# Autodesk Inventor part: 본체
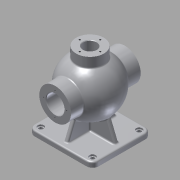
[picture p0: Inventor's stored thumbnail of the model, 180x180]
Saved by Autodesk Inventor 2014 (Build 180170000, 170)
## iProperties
Created: 2015-10
Part Number: 본체
Material: Aluminum 6061
Document SubType Name: Modeling
Designer: youjin15
Density: 2.71 g/cm^3
Appearance: Aluminum - Flat
Mass: 1509.57 g
Surface Area: 1153.7 cm^2
Volume: 557.037 cm^3
Author: youjin15
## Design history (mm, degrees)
sketch "Sketch1"
  geometry: L1 (45.5, -62.5)-(-45.5, -62.5); L2 (-57.5, -50.5)-(-57.5, 50.5); L3 (-45.5, 62.5)-(45.5, 62.5); L4 (57.5, 50.5)-(57.5, -50.5); L5 (57.5, -62.5)-(-57.5, 62.5); L6 (-57.5, -62.5)-(57.5, 62.5); A1 r 12 centre (-45.5, 50.5) between (-45.5, 62.5) and (-57.5, 50.5); A2 r 12 centre (45.5, 50.5) between (57.5, 50.5) and (45.5, 62.5); A3 r 12 centre (45.5, -50.5) between (45.5, -62.5) and (57.5, -50.5); A4 r 12 centre (-45.5, -50.5) between (-57.5, -50.5) and (-45.5, -62.5); 1 further point
  constraints: 12 end point, 8 point on circle, 8 point on line, 8 tangent, 4 centre point, 3 equal radius, 2 midpoint, 2 parallel, 1 horizontal, 1 perpendicular
  dimensions: "d0" = 115 distance of L5.end L6.end; "d1" = 125 distance of L6.start L5.end; "d2" = 12 radius of A1
extrude "Extrusion1" new body sketch "Sketch1" distance "d3" = 10; taper "d4" = 0 deg
sketch "Sketch2"
  geometry: L1 (53, 85)-(-53, 85); L2 (45.5, 0)-(-45.5, 0) reference; A1 r 53 centre (0, 85) between (53, 85) and (-53, 85); 4 further points
  constraints: 2 end point, 2 midpoint, 2 point on circle, 2 vertical alignment, 1 centre point, 1 horizontal
  dimensions: "d5" = 106 distance of L1.start L1.end; "d6" = 53 radius of A1; "d7" = 85 distance between parallel lines of L2 L1; "d9" = 43 distance of A1.centre point (0, 128)
revolve "Revolution1" sketch "Sketch2" stored, may be unused: angle "d10" = 90 deg
sketch "Sketch3"
  geometry: L1 (68, 85)-(-68, 85); L2 (-45.5, 0)-(45.5, 0) reference; L3 (68, 85)-(68, 116); L4 (68, 116)-(42.988, 116); L5 (-68, 85)-(-68, 116); L6 (-68, 116)-(-42.988, 116); A1 r 53 centre (0, 85) between (42.988, 116) and (-42.988, 116) reference; A2 r 53 centre (0, 85) between (-42.988, 116) and (-53, 85); A3 r 53 centre (0, 85) between (53, 85) and (42.988, 116); 2 further points
  constraints: 10 end point, 8 point on circle, 4 perpendicular, 2 centre point, 2 coincident, 2 concentric, 1 collinear, 1 horizontal, 1 midpoint, 1 point on line, 1 vertical alignment
  dimensions: "d11" = 136 distance of L1.start L1.end; "d12" = 85 distance between parallel lines of L2 L1; "d13" = 62 diameter of L4 L1
revolve "Revolution2" sketch "Sketch3" stored, may be unused: angle "d14" = 90 deg
hole "Hole1" diameter "d17" = 35; stored, may be unused: countersink angle "d21" = 90 deg, drill point angle "d23" = 0 deg; dims "d15" = 10, "d16" = 10, "d18" = 6, "d19" = 4, "d20" = 2, "d22" = 8
sketch "Sketch4"
  geometry: L1 (-43, 85)-(43, 85); L2 (45.5, 0)-(-45.5, 0) reference; A1 r 53 centre (0, 85) between (42.988, 116) and (42.988, 54) reference; A2 r 43 centre (0, 85) between (43, 85) and (-43, 85); 2 further points
  constraints: 2 end point, 2 point on circle, 1 centre point, 1 coincident, 1 horizontal, 1 midpoint, 1 vertical alignment
  dimensions: "d24" = 43 radius of A2; "d25" = 85 distance between parallel lines of L2 L1
revolve "Revolution3" sketch "Sketch4" stored, may be unused: angle "d26" = 90 deg
sketch "Sketch5"
  geometry: L1 (42.988, 116)-(42.988, 54) reference; L2 (68, 54)-(68, 116) reference; L3 (39.278, 102.5)-(68, 102.5) reference; L4 (39.278, 67.5)-(68, 67.5) reference; L5 (42.988, 116)-(68, 116) reference; L6 (68, 116)-(68, 102.5) reference; L7 (68, 102.5)-(39.278, 102.5) reference; L8 (-39.278, 102.5)-(-68, 102.5) reference; L9 (-68, 102.5)-(-68, 116) reference; L10 (-68, 116)-(-42.988, 116) reference; L11 (68, 54)-(42.988, 54) reference; L12 (-42.988, 54)-(-68, 54) reference; L13 (-68, 54)-(-68, 67.5) reference; L14 (-68, 67.5)-(-39.278, 67.5) reference; L15 (39.278, 67.5)-(68, 67.5) reference; L16 (68, 67.5)-(68, 54) reference; L17 (57.5, 10)-(57.5, 0) reference; L18 (57.5, 0)-(-57.5, 0) reference; L19 (-57.5, 0)-(-57.5, 10) reference; L20 (-57.5, 10)-(57.5, 10) reference; L21 (0, 85)-(68, 85); L22 (52, 85)-(52, 103.5); L23 (52, 103.5)-(50.25, 103.5); L24 (50.25, 103.5)-(50.25, 85); A1 r 43 centre (0, 85) between (39.278, 102.5) and (-39.278, 102.5) reference; A2 r 53 centre (0, 85) between (42.988, 116) and (-42.988, 116) reference; A3 r 53 centre (0, 85) between (-42.988, 54) and (42.988, 54) reference; A4 r 43 centre (0, 85) between (-39.278, 67.5) and (39.278, 67.5) reference; 1 further point
  constraints: 8 end point, 3 perpendicular, 2 point on line, 1 midpoint
  dimensions: "d27" = 1.75 distance of L22.end L23.end; "d28" = 16 distance between parallel lines of L2 L22; "d29" = 37 diameter of L23 L21
revolve "Revolution4" sketch "Sketch5" stored, may be unused: angle "d30" = 90 deg
workplane "Work Plane1"
sketch "Sketch6"
  geometry: C1 r 27 at (0, 0); 1 further point
  constraints: 1 centre point, 1 coincident
  dimensions: "d33" = 54 diameter of C1
extrude "Extrusion2" join sketch "Sketch6" stored distance "d34" = 10; taper "d35" = 0 deg
hole "Hole2" diameter "d38" = 26; stored, may be unused: countersink angle "d42" = 90 deg, drill point angle "d44" = 0 deg; dims "d36" = 10, "d37" = 10, "d39" = 6, "d40" = 4, "d41" = 2, "d43" = 8
sketch "Sketch11"
  geometry: L1 (-27, 130.607)-(-27, 150) reference; L2 (-27, 150)-(-13, 150) reference; L3 (-13, 150)-(-13, 125.988) reference; L4 (-39.278, 102.5)-(-68, 102.5) reference; L5 (-68, 102.5)-(-68, 116) reference; L6 (-68, 116)-(-42.988, 116) reference; L7 (52, 103.5)-(50.25, 103.5) reference; L8 (50.25, 103.5)-(50.25, 102.5) reference; L9 (50.25, 102.5)-(39.278, 102.5) reference; L10 (13, 125.988)-(13, 150) reference; L11 (13, 150)-(27, 150) reference; L12 (27, 150)-(27, 130.607) reference; L13 (42.988, 116)-(68, 116) reference; L14 (68, 116)-(68, 102.5) reference; L15 (68, 102.5)-(52, 102.5) reference; L16 (52, 102.5)-(52, 103.5) reference; L17 (50.25, 66.5)-(52, 66.5) reference; L18 (52, 66.5)-(52, 67.5) reference; L19 (52, 67.5)-(68, 67.5) reference; L20 (68, 67.5)-(68, 54) reference; L21 (68, 54)-(42.988, 54) reference; L22 (-42.988, 54)-(-68, 54) reference; L23 (-68, 54)-(-68, 67.5) reference; L24 (-68, 67.5)-(-39.278, 67.5) reference; L25 (39.278, 67.5)-(50.25, 67.5) reference; L26 (50.25, 67.5)-(50.25, 66.5) reference; L27 (57.5, 10)-(57.5, 0) reference; L28 (57.5, 0)-(-57.5, 0) reference; L29 (-57.5, 0)-(-57.5, 10) reference; L30 (-57.5, 10)-(57.5, 10) reference; L31 (-47.5, 10)-(-29.744, 53.947); L32 (29.744, 53.947)-(47.5, 10); L33 (-47.5, 10)-(47.5, 10); A1 r 53 centre (0, 85) between (-27, 130.607) and (-42.988, 116) reference; A2 r 43 centre (0, 85) between (-13, 125.988) and (-39.278, 102.5) reference; A3 r 43 centre (0, 85) between (39.278, 102.5) and (13, 125.988) reference; A4 r 53 centre (0, 85) between (42.988, 116) and (27, 130.607) reference; A5 r 53 centre (0, 85) between (-42.988, 54) and (42.988, 54) reference; A6 r 43 centre (0, 85) between (-39.278, 67.5) and (39.278, 67.5) reference; 1 further point
  constraints: 6 end point, 2 point on circle, 2 point on line
  dimensions: "d61" = 10 distance of L29.end L31.start; "d62" = 10 distance of L27.start L32.end; "d63" = 22 deg angle of L27 L32; "d64" = 22 deg angle of L29 L31
extrude "Extrusion5" join sketch "Sketch11" stored distance "d65" = 8; taper "d66" = 0 deg
sketch "Sketch12"
  geometry: L1 (-13, 150)-(-13, 125.988) reference; L2 (13, 125.988)-(13, 150) reference; L3 (13, 150)-(27, 150) reference; L4 (27, 150)-(27, 130.607) reference; L5 (4, 32.151)-(4, 10) reference; L6 (4, 10)-(62.5, 10) reference; L7 (62.5, 10)-(62.5, 0) reference; L8 (62.5, 0)-(-62.5, 0) reference; L9 (-62.5, 0)-(-62.5, 10) reference; L10 (-62.5, 10)-(-4, 10) reference; L11 (-4, 10)-(-4, 32.151) reference; L12 (-27, 130.607)-(-27, 150) reference; L13 (-27, 150)-(-13, 150) reference; L14 (-52.5, 10)-(-33.226, 57.705); L15 (33.226, 57.705)-(52.5, 10); A1 r 43 centre (0, 85) between (-13, 125.988) and (13, 125.988) reference; A2 r 53 centre (0, 85) between (4, 32.151) and (27, 130.607) reference; A3 r 53 centre (0, 85) between (-27, 130.607) and (-4, 32.151) reference; 1 further point
  constraints: 4 end point, 2 point on circle, 2 point on line
  dimensions: "d67" = 10 distance of L6.end L15.end; "d68" = 22 deg angle of L7 L15; "d69" = 10 distance of L9.end L14.start; "d70" = 22 deg angle of L9 L14
extrude "Extrusion6" join sketch "Sketch12" stored distance "d71" = 8; taper "d72" = 0 deg
sketch "Sketch13"
  geometry: A1 r 12 centre (45.5, 50.5) between (57.5, 50.5) and (45.5, 62.5) reference; 5 further points
  constraints: 2 horizontal alignment, 2 vertical alignment, 1 coincident
  dimensions: "d73" = 91 distance of point (45.5, 50.5) point (-45.5, 50.5); "d74" = 101 distance of point (45.5, -50.5) point (45.5, 50.5)
hole "Hole3" sketch "Sketch13" at (-45.5, 50.5), (45.5, 50.5), (-45.5, -50.5), (45.5, -50.5) diameter "d75" = 8; stored, may be unused: countersink angle "d79" = 90 deg, drill point angle "d81" = 0 deg; dims "d76" = 6, "d77" = 12, "d78" = 3, "d80" = 8
sketch "Sketch14" dims "d82" = 45
  geometry: C1 r 31 at (0, 0) reference; 3 further points
  constraints: 2 vertical alignment, 1 coincident, 2 other
hole "Hole4" sketch "Sketch14" at (0, 22.5) diameter "d83" = 3.242; stored, may be unused: countersink angle "d87" = 90 deg, drill point angle "d89" = 118 deg; dims "d84" = 12, "d85" = 12, "d86" = 3, "d88" = 15
pattern_circular "Circular Pattern1" dims angle "d91" = 360 deg
sketch "Sketch15" dims "d93" = 48
  geometry: C1 r 31 at (0, 0) reference; 3 further points
  constraints: 2 vertical alignment, 1 coincident, 2 other
hole "Hole5" sketch "Sketch15" at (0, 24) diameter "d94" = 3.242; stored, may be unused: countersink angle "d98" = 90 deg, drill point angle "d100" = 118 deg; dims "d95" = 16, "d96" = 4, "d97" = 2, "d99" = 19
pattern_circular "Circular Pattern2" dims angle "d102" = 360 deg
sketch "Sketch16" dims "d104" = 40
  geometry: C1 r 27 at (0, 0) reference; 2 further points
  constraints: 2 vertical alignment, 1 coincident, 2 other
hole "Hole6" sketch "Sketch16" at (0, 20) diameter "d105" = 3.242; stored, may be unused: countersink angle "d109" = 90 deg, drill point angle "d111" = 118 deg; dims "d106" = 9, "d107" = 4, "d108" = 2, "d110" = 11
pattern_circular "Circular Pattern3" dims angle "d113" = 360 deg
workplane "Work Plane2"
sketch "Sketch17"
  geometry: L1 (68, 100.232)-(68, 69.768) reference; L2 (68, 69.768)-(42.988, 69.768) reference; L3 (4, 39.569)-(4, 10) reference; L4 (4, 10)-(57.5, 10) reference; L5 (57.5, 10)-(57.5, 0) reference; L6 (57.5, 0)-(-57.5, 0) reference; L7 (-57.5, 0)-(-57.5, 10) reference; L8 (-57.5, 10)-(-4, 10) reference; L9 (-4, 10)-(-4, 39.569) reference; L10 (-42.988, 69.768)-(-68, 69.768) reference; L11 (-68, 69.768)-(-68, 100.232) reference; L12 (-68, 100.232)-(-42.988, 100.232) reference; L13 (42.988, 100.232)-(68, 100.232) reference; L14 (0, 150)-(0, 130.607) reference; C1 r 33.466 at (0, 85) reference; A1 r 45.607 centre (0, 85) between (4, 39.569) and (42.988, 69.768) reference; A2 r 45.607 centre (0, 85) between (-42.988, 69.768) and (-4, 39.569) reference; A3 r 45.607 centre (0, 85) between (0, 130.607) and (-42.988, 100.232) reference; A4 r 45.607 centre (0, 85) between (42.988, 100.232) and (0, 130.607) reference; 2 further points
  constraints: 1 vertical alignment, 1 other
  dimensions: "d116" = 10 distance of point (0, 140) L14.start
emboss "Emboss1" sketch "Sketch17" dims "d0" = 115, "d1" = 125, "d2" = 12, "d117" = 0.5, "d118" = 0
fillet "Fillet1" dims "d119" = 3
chamfer "Chamfer1" distance "d120" = 1; stored, may be unused: second distance "d121" = 2, angle "d122" = 45 deg
body "Solid1"
node "Projected Loop1"
node "Project Cut Edges1"
node "Project Cut Edges4"
node "Project Cut Edges5"
node "Project Cut Edges6"
other parameters: "d115" = -27
